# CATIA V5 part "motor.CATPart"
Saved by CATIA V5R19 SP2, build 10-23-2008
Part number: motor
Bounding box of the stored display mesh (mm): x -841 to 0, y -350.96 to 750, z 0 to 737.14
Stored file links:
  C:\BEHROOZ\catia learning\tarh haye mashin\hb\motor.CATPart
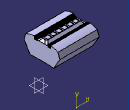
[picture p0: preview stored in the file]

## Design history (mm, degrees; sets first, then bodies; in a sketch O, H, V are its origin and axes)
Body1 (main body)
  Sketch1 on yz-plane, origin (0, 0, 0), H (0, 1, 0), V (0, 0, 1)
    point P1 (0, 688.0779)
    line L1 (0, 688.0779) -> (-92.4167, 688.1938)
    line L2 (-92.4167, 688.1938) -> (-127.0005, 730.7328)
    arc A1 centre (-144.2784, 336.3879) radius 394.7232 from (-127.0005, 730.7328) to (-317.1266, 691.2539) ccw
    line L3 (-317.1266, 691.2539) -> (-350.9602, 579.3489)
    line L4 (-350.9602, 579.3489) -> (-233.2136, 376.3238)
    line L5 (-233.2136, 376.3238) -> (0, 385.7373)
    point P8 (0, 385.7373)
    point P9 (0, 688.0779)
    point P16 (0, 385.7373)
    line L6 (0, 688.0779) -> (92.4167, 688.1938)
    line L7 (92.4167, 688.1938) -> (127.0005, 730.7328)
    arc A2 centre (144.2784, 336.3879) radius 394.7232 from (127.0005, 730.7328) to (317.1266, 691.2539) cw
    line L8 (317.1266, 691.2539) -> (350.9602, 579.3489)
    line L9 (350.9602, 579.3489) -> (233.2136, 376.3238)
    line L10 (233.2136, 376.3238) -> (0, 385.7373)
    coincidence: P1 P9, P8 P16
  Pad1: profile Sketch1, direction (1, 0, 0), length -67, opposite side length 841
  Sketch2 on face of Pad1 from Sketch1.L1, origin (0, 0.8634, 688.0768), H (-1, 0, 0), V (0, -1, 0.0013)
    projected line E1 (841, 0.8634) -> (841, 93.2801) from edge [start face of Pad1 | face of Pad1 from Sketch1.L1]
    projected line E2 (841, -91.553) -> (841, 0.8634) from edge [start face of Pad1 | face of Pad1 from Sketch1.L6]
    projected line E3 (67, 0.8634) -> (67, 93.2801) from edge [face of Pad1 from Sketch1.L1 | end face of Pad1]
    projected line E4 (67, -91.553) -> (67, 0.8634) from edge [face of Pad1 from Sketch1.L6 | end face of Pad1]
    projected line E5 (841, -91.553) -> (67, -91.553) from edge [face of Pad1 from Sketch1.L6 | face of Pad1 from Sketch1.L7]
    projected line E6 (841, 93.2801) -> (67, 93.2801) from edge [face of Pad1 from Sketch1.L2 | face of Pad1 from Sketch1.L1]
  Pad2: profile Sketch2, direction (0, -0.0013, -1), length -49
  Chamfer1: length 41, angle 45, on edge [face of Pad2 from Sketch2.E6 | end face of Pad2]; edge [face of Pad2 from Sketch2.E5 | end face of Pad2]
  Chamfer2: length 41, angle 45, on edge [face of Pad2 | end face of Pad2]
  Chamfer3: length 41, angle 45, on edge [face of Pad2 | end face of Pad2]
  Sketch3 on end face of Pad2, origin (0, 0.9249, 737.0767), H (-1, 0, 0), V (0, -1, 0.0013)
    line L1 (150, 40) -> (210, 40)
    line L2 (220, 30) -> (220, -30)
    line L3 (210, -40) -> (150, -40)
    line L4 (140, -30) -> (140, 30)
    arc A1 centre (150, 30) radius 10 from (150, 40) to (140, 30) ccw
    arc A2 centre (210, 30) radius 10 from (210, 40) to (220, 30) cw
    arc A3 centre (210, -30) radius 10 from (220, -30) to (210, -40) cw
    arc A4 centre (150, -30) radius 10 from (150, -40) to (140, -30) cw
    line L5 (260, 40) -> (320, 40)
    line L6 (330, 30) -> (330, -30)
    line L7 (320, -40) -> (260, -40)
    line L8 (250, -30) -> (250, 30)
    arc A5 centre (260, 30) radius 10 from (260, 40) to (250, 30) ccw
    arc A6 centre (320, 30) radius 10 from (320, 40) to (330, 30) cw
    arc A7 centre (320, -30) radius 10 from (330, -30) to (320, -40) cw
    arc A8 centre (260, -30) radius 10 from (260, -40) to (250, -30) cw
    line L9 (370, 40) -> (430, 40)
    line L10 (440, 30) -> (440, -30)
    line L11 (430, -40) -> (370, -40)
    line L12 (360, -30) -> (360, 30)
    arc A9 centre (370, 30) radius 10 from (370, 40) to (360, 30) ccw
    arc A10 centre (430, 30) radius 10 from (430, 40) to (440, 30) cw
    arc A11 centre (430, -30) radius 10 from (440, -30) to (430, -40) cw
    arc A12 centre (370, -30) radius 10 from (370, -40) to (360, -30) cw
    line L13 (480, 40) -> (540, 40)
    line L14 (550, 30) -> (550, -30)
    line L15 (540, -40) -> (480, -40)
    line L16 (470, -30) -> (470, 30)
    arc A13 centre (480, 30) radius 10 from (480, 40) to (470, 30) ccw
    arc A14 centre (540, 30) radius 10 from (540, 40) to (550, 30) cw
    arc A15 centre (540, -30) radius 10 from (550, -30) to (540, -40) cw
    arc A16 centre (480, -30) radius 10 from (480, -40) to (470, -30) cw
    line L17 (590, 40) -> (650, 40)
    line L18 (660, 30) -> (660, -30)
    line L19 (650, -40) -> (590, -40)
    line L20 (580, -30) -> (580, 30)
    arc A17 centre (590, 30) radius 10 from (590, 40) to (580, 30) ccw
    arc A18 centre (650, 30) radius 10 from (650, 40) to (660, 30) cw
    arc A19 centre (650, -30) radius 10 from (660, -30) to (650, -40) cw
    arc A20 centre (590, -30) radius 10 from (590, -40) to (580, -30) cw
    line L21 (700, 40) -> (760, 40)
    line L22 (770, 30) -> (770, -30)
    line L23 (760, -40) -> (700, -40)
    line L24 (690, -30) -> (690, 30)
    arc A21 centre (700, 30) radius 10 from (700, 40) to (690, 30) ccw
    arc A22 centre (760, 30) radius 10 from (760, 40) to (770, 30) cw
    arc A23 centre (760, -30) radius 10 from (770, -30) to (760, -40) cw
    arc A24 centre (700, -30) radius 10 from (700, -40) to (690, -30) cw
  Pocket1: profile Sketch3, direction (0, -0.0013, -1), length -49, opposite side length -4
  Fillet1: radius 42, on edge [face of Chamfer1 | face of Chamfer2] (x2); edge [face of Chamfer1 | face of Chamfer3] (x2)
  Fillet2: radius 4, on end face of Pad2
  Fillet3: radius 4, on start face of Pocket1 (x6); edge [face of Fillet2 | start face of Pocket1]
  Chamfer4: length 47, angle 19, on edge [face of Pad1 from Sketch1.L7 | face of Pad1 from Sketch1.A2]; edge [face of Pad1 from Sketch1.A1 | face of Pad1 from Sketch1.L2]
  Plane1: stored without definition
  Sketch4 on end face of Pad2, origin (0, 0.9249, 737.0767), H (-1, 0, 0), V (0, -1, 0.0013)
    line L1 (841, -120) -> (67, -120)
    line L2 (841, -130.0768) -> (67, -130.0768)
    line L3 (841, -140.1536) -> (67, -140.1536)
    line L4 (841, -150.2304) -> (67, -150.2304)
    line L5 (841, -160.3072) -> (67, -160.3072)
    line L6 (841, -170.384) -> (67, -170.384)
    line L7 (841, 100) -> (67, 100)
    line L8 (841, 110.0768) -> (67, 110.0768)
    line L9 (841, 120.1536) -> (67, 120.1536)
    line L10 (841, 130.2304) -> (67, 130.2304)
    line L11 (841, 140.3072) -> (67, 140.3072)
    line L12 (841, 150.384) -> (67, 150.384)
  Pocket2: profile Sketch4, direction (0, -0.0013, -1), length -49, opposite side length -58, thin wall 1
  Sketch5 on Plane1, origin (0, 750, 0), H (-1, 0, 0), V (0, 0, 1)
